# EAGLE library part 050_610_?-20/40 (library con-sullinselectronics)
.050 DIP EDGE CARD CONNECTOR .050 [1.27mm] CONTACT CENTERS .610" INSULATEOR HEIGHT Source: .050 DIP EDGE CARD.pdf
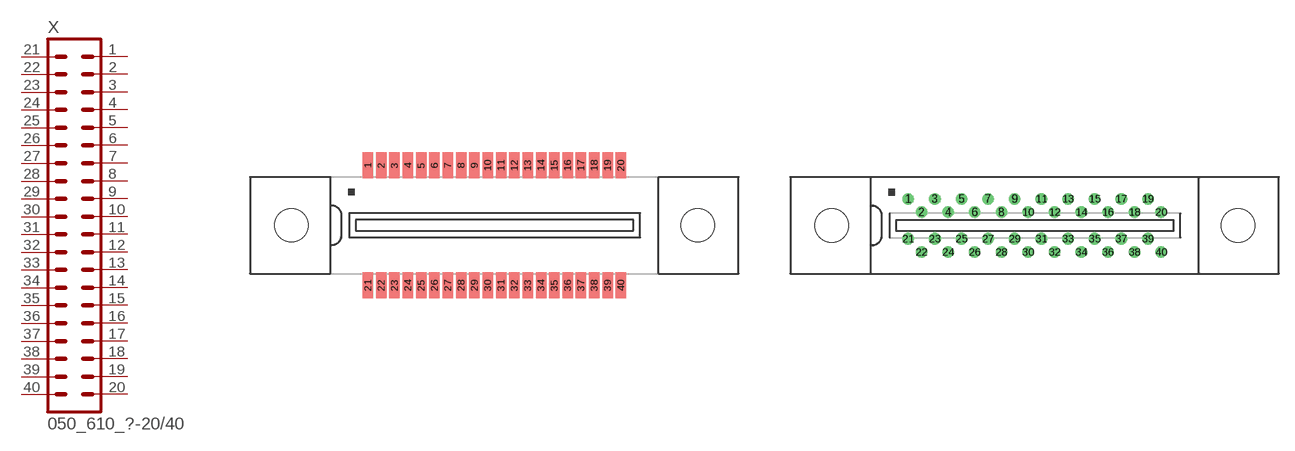
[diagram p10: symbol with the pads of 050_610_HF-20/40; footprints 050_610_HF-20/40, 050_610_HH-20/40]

Designator prefix X

## 050_610_HF-20/40 (OC_FARNELL: unknown; OC_NEWARK: unknown)  [050_610_HF-20/40]
1  1  pas
2  2  pas
3  3  pas
4  4  pas
5  5  pas
6  6  pas
7  7  pas
8  8  pas
9  9  pas
10  10  pas
11  11  pas
12  12  pas
13  13  pas
14  14  pas
15  15  pas
16  16  pas
17  17  pas
18  18  pas
19  19  pas
20  20  pas
21  21  pas
22  22  pas
23  23  pas
24  24  pas
25  25  pas
26  26  pas
27  27  pas
28  28  pas
29  29  pas
30  30  pas
31  31  pas
32  32  pas
33  33  pas
34  34  pas
35  35  pas
36  36  pas
37  37  pas
38  38  pas
39  39  pas
40  40  pas

## 050_610_HH-20/40 (OC_FARNELL: unknown; OC_NEWARK: unknown)  [050_610_HH-20/40]
Pads as for 050_610_HF-20/40

## Footprint 050_610_HF-20/40 (pad centres in mm)
.050 DIP EDGE CARD CONNECTOR SURFACE MOUNT .050 [1.27mm] CONTACT CENTERS .610" INSULATEOR HEIGHT Source: .050 DIP EDGE CARD.pdf
smd 1 x 2.5: 1 -12.065,5.715; 2 -10.795,5.715; 3 -9.525,5.715; 4 -8.255,5.715; 5 -6.985,5.715; 6 -5.715,5.715; 7 -4.445,5.715; 8 -3.175,5.715; 9 -1.905,5.715; 10 -0.635,5.715; 11 0.635,5.715; 12 1.905,5.715; 13 3.175,5.715; 14 4.445,5.715; 15 5.715,5.715; 16 6.985,5.715; 17 8.255,5.715; 18 9.525,5.715; 19 10.795,5.715; 20 12.065,5.715; 21 -12.065,-5.715; 22 -10.795,-5.715; 23 -9.525,-5.715; 24 -8.255,-5.715; 25 -6.985,-5.715; 26 -5.715,-5.715; 27 -4.445,-5.715; 28 -3.175,-5.715; 29 -1.905,-5.715; 30 -0.635,-5.715; 31 0.635,-5.715; 32 1.905,-5.715; 33 3.175,-5.715; 34 4.445,-5.715; 35 5.715,-5.715; 36 6.985,-5.715; 37 8.255,-5.715; 38 9.525,-5.715; 39 10.795,-5.715; 40 12.065,-5.715
hole 3.18 at -19.38,0
hole 3.18 at 19.38,0

## Footprint 050_610_HH-20/40 (pad centres in mm)
.050 DIP EDGE CARD CONNECTOR STAGGERED DIP SOLDER .050 [1.27mm] CONTACT CENTERS .610" INSULATEOR HEIGHT Source: .050 DIP EDGE CARD.pdf
drill 0.6 pad 1 round: 1 -12.065,2.54; 2 -10.795,1.27; 3 -9.525,2.54; 4 -8.255,1.27; 5 -6.985,2.54; 6 -5.715,1.27; 7 -4.445,2.54; 8 -3.175,1.27; 9 -1.905,2.54; 10 -0.635,1.27; 11 0.635,2.54; 12 1.905,1.27; 13 3.175,2.54; 14 4.445,1.27; 15 5.715,2.54; 16 6.985,1.27; 17 8.255,2.54; 18 9.525,1.27; 19 10.795,2.54; 20 12.065,1.27; 21 -12.065,-1.27; 22 -10.795,-2.54; 23 -9.525,-1.27; 24 -8.255,-2.54; 25 -6.985,-1.27; 26 -5.715,-2.54; 27 -4.445,-1.27; 28 -3.175,-2.54; 29 -1.905,-1.27; 30 -0.635,-2.54; 31 0.635,-1.27; 32 1.905,-2.54; 33 3.175,-1.27; 34 4.445,-2.54; 35 5.715,-1.27; 36 6.985,-2.54; 37 8.255,-1.27; 38 9.525,-2.54; 39 10.795,-1.27; 40 12.065,-2.54
hole 3.18 at -19.38,0
hole 3.18 at 19.38,0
